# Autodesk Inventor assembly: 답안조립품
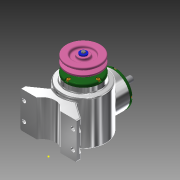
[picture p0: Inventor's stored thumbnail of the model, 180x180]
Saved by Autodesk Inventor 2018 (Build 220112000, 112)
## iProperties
Created: 2021-04
Part Number: 답안조립품
Material: 일반
Document SubType Name: Assembly
Designer: home
Author: home
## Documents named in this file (17)
- C:\Users\home\Desktop\710407V1015\답안조립품.iam
- C:\Users\home\Desktop\710407V1015\본체.ipt
- C:\Users\home\Desktop\710407V1015\커버.ipt
- C:\Users\home\Desktop\710407V1015\베어링 6203.ipt
- C:\Users\home\Desktop\710407V1015\오일실 17 x 32 x 8.ipt
- C:\Users\home\Desktop\710407V1015\메인 축.ipt
- 메인 축.ipt
- C:\Users\home\Desktop\710407V1015\서브 축.ipt
- 서브 축.ipt
- C:\Users\home\Desktop\710407V1015\메인 베벨기어.ipt
- C:\Users\home\Desktop\710407V1015\키 5 x 5 x 14.ipt
- C:\Users\home\Desktop\710407V1015\키 4 x 4 x 14.ipt
- C:\Users\home\Desktop\710407V1015\서브 베벨기어.ipt
- C:\Users\home\Desktop\710407V1015\V-벨트풀리.ipt
- C:\Users\home\Desktop\710407V1015\와셔 4 x 16.ipt
- C:\Users\home\Desktop\710407V1015\육각볼트 M4 x 8.ipt
- C:\Users\home\Desktop\710407V1015\볼트 M4 x 10.ipt
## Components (1 placed, 1 different names)
1. V-벨트풀리:1 — 각도:5
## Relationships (1: Angle 1)
- 각도:5 [Angle]: V-벨트풀리:1
